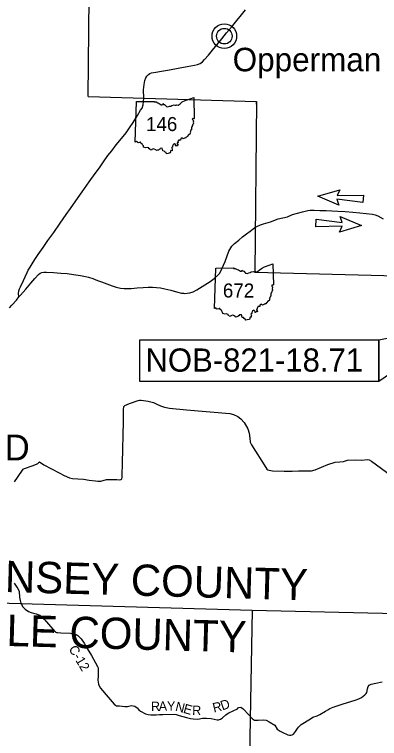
# Model space of a CAD drawing. Extents: x 0 to 34, y 0 to 22.
# Drawn here: x 22.078 to 24.277, y 13.537 to 17.905 of the extents above; entities that cross this region are included whole.
import ezdxf

# ---------------------------------------------------------------- set-up
doc = ezdxf.new("R2010")
doc.units = 0
for name, color, linetype in [('Default', 7, 'Continuous'), ('GM_X_County_Road_Text', 7, 'Continuous'), ('GM_X_State_Route', 7, 'Continuous'), ('GM_X_Township', 7, 'Continuous'), ('GM_X_Unincorporated', 7, 'Continuous'), ('GM_X_Unincorporated_Text', 7, 'Continuous'), ('TX_P_1', 7, 'Continuous')]:
    doc.layers.add(name, color=color, linetype=linetype)

msp = doc.modelspace()

# ---------------------------------------------------------------- linework, layer by layer
at = {"layer": 'Default'}
for p, q in [((22.8057, 17.1347), (22.8136, 17.3788)), ((23.9046, 16.8078), (24.0377, 16.8476)), ((24.0377, 16.8476), (24.0222, 16.8128)), ((24.0222, 16.8128), (24.1797, 16.8155)), ((24.1797, 16.8155), (24.1773, 16.7708)), ((24.0327, 16.7539), (23.9046, 16.8078)), ((24.1773, 16.7708), (24.0209, 16.7904)), ((24.0209, 16.7904), (24.0327, 16.7539)), ((24.0527, 16.6499), (24.0409, 16.6862)), ((24.0409, 16.6862), (24.169, 16.6324)), ((23.8939, 16.6247), (23.8963, 16.6694)), ((23.8963, 16.6694), (24.0527, 16.6499)), ((24.0514, 16.6272), (23.8939, 16.6247)), ((24.169, 16.6324), (24.0358, 16.5925)), ((24.0358, 16.5925), (24.0514, 16.6272)), ((23.2832, 16.1306), (23.291, 16.3746))]:
    msp.add_line(p, q, dxfattribs=at)
for points in [[(22.8136, 17.3788), (22.9218, 17.3803), (22.9201, 17.3774), (22.9303, 17.3768), (22.9411, 17.3715), (22.9503, 17.3683), (22.9615, 17.3605), (22.9682, 17.3606), (22.9711, 17.367), (22.9762, 17.362), (22.9823, 17.3612), (22.9929, 17.3495), (23.0016, 17.347), (23.012, 17.351), (23.0197, 17.3516), (23.0255, 17.3556), (23.0403, 17.359), (23.0445, 17.3569), (23.0523, 17.3574), (23.0563, 17.3588), (23.0632, 17.3575), (23.0752, 17.3664), (23.0876, 17.3768), (23.1068, 17.3867), (23.1352, 17.396), (23.1579, 17.4044), (23.1611, 17.2778)], [(23.1611, 17.2778), (23.1578, 17.276), (23.1526, 17.2768), (23.1491, 17.2733), (23.1535, 17.2674), (23.1555, 17.2611), (23.1537, 17.2542), (23.1555, 17.2485), (23.1543, 17.2438), (23.151, 17.239), (23.1499, 17.2345), (23.1471, 17.2297), (23.1473, 17.2271), (23.1447, 17.225), (23.1452, 17.217), (23.1438, 17.2127), (23.1443, 17.2089), (23.14, 17.2079), (23.141, 17.2048), (23.1382, 17.2023), (23.1388, 17.1982), (23.1357, 17.1955), (23.1387, 17.1902), (23.1363, 17.1885), (23.1343, 17.1821), (23.1288, 17.1807), (23.1179, 17.169), (23.114, 17.1645), (23.1096, 17.1634), (23.1072, 17.1588), (23.1018, 17.1588), (23.0937, 17.1556), (23.0884, 17.161), (23.0792, 17.1545), (23.0782, 17.1468), (23.0666, 17.1471), (23.067, 17.1432), (23.0644, 17.1421), (23.0621, 17.1383), (23.0634, 17.1314), (23.0579, 17.1297), (23.0586, 17.1257), (23.0621, 17.1233), (23.0637, 17.1157), (23.0579, 17.1172), (23.0531, 17.1108), (23.0482, 17.1123), (23.0498, 17.1177), (23.0416, 17.1243), (23.0338, 17.1191), (23.0297, 17.1107), (23.0297, 17.105), (23.0238, 17.1017), (23.0276, 17.0937), (23.0269, 17.0883), (23.027, 17.083), (23.0197, 17.0833), (23.0153, 17.0692)], [(23.0153, 17.0692), (23.0027, 17.0666), (22.994, 17.065), (22.9909, 17.0713), (22.9846, 17.0747), (22.9805, 17.0811), (22.9715, 17.0819), (22.9694, 17.0908), (22.9684, 17.0979), (22.9561, 17.0961), (22.9528, 17.0918), (22.9484, 17.0906), (22.9458, 17.0862), (22.9398, 17.0858), (22.9335, 17.0837), (22.9293, 17.088), (22.9188, 17.0924), (22.9141, 17.0946), (22.9043, 17.0912), (22.9022, 17.0871), (22.8944, 17.0889), (22.8925, 17.0935), (22.8878, 17.0949), (22.8868, 17.0997), (22.8766, 17.1023), (22.8689, 17.1013), (22.8552, 17.1052), (22.8544, 17.1116), (22.8497, 17.1194), (22.8474, 17.1248), (22.8387, 17.1288), (22.8369, 17.1353), (22.8342, 17.1351), (22.8317, 17.1325), (22.822, 17.1313), (22.8182, 17.1339), (22.8128, 17.1385), (22.8057, 17.1347)], [(22.104, 16.2014), (22.1143, 16.2115), (22.1452, 16.2469), (22.1757, 16.2842), (22.2009, 16.3131), (22.222, 16.3359), (22.2326, 16.3446), (22.2432, 16.3489), (22.2545, 16.3508), (22.2712, 16.3509), (22.3125, 16.3477), (22.3568, 16.3452), (22.395, 16.3416), (22.4322, 16.3361), (22.475, 16.3299), (22.5064, 16.3251), (22.5231, 16.3211), (22.55, 16.3114), (22.5777, 16.3005), (22.6028, 16.2915), (22.6331, 16.2803), (22.6665, 16.2684), (22.6907, 16.2605), (22.7169, 16.2542), (22.7389, 16.2517), (22.7597, 16.2518), (22.7809, 16.2527), (22.8161, 16.2559), (22.8521, 16.2587), (22.8827, 16.2607), (22.9092, 16.2605), (22.9342, 16.2583), (22.957, 16.2554), (22.9843, 16.2491), (23.0191, 16.2413), (23.0544, 16.2324), (23.0839, 16.2242), (23.0955, 16.2228), (23.101, 16.222), (23.118, 16.2229), (23.1351, 16.2264), (23.1551, 16.2325), (23.1759, 16.2432), (23.2573, 16.2946), (23.2807, 16.3131), (23.2985, 16.3286), (23.3141, 16.345), (23.3262, 16.3706), (23.3461, 16.4146), (23.3695, 16.4766), (23.3869, 16.5075), (23.4032, 16.5238), (23.4291, 16.5437), (23.4522, 16.5629), (23.476, 16.5821), (23.4969, 16.5973), (23.5243, 16.6175), (23.5267, 16.6194), (23.5381, 16.6261), (23.5598, 16.6357), (23.5771, 16.6421), (23.6205, 16.6549), (23.6673, 16.6712), (23.7218, 16.6847), (23.7536, 16.6987), (23.8129, 16.7147), (23.8288, 16.7193), (23.8447, 16.7221), (23.8594, 16.7236), (23.8833, 16.7234), (23.9178, 16.7232), (23.9552, 16.7222), (23.9893, 16.7205), (24.0264, 16.718), (24.0692, 16.716), (24.1155, 16.7128), (24.1583, 16.7092), (24.1969, 16.7052), (24.2348, 16.7005), (24.2515, 16.6964), (24.2666, 16.6893), (24.2993, 16.6724)], [(23.291, 16.3746), (23.3992, 16.3762), (23.3976, 16.3732), (23.4077, 16.3726), (23.4186, 16.3674), (23.4278, 16.3641), (23.4389, 16.3564), (23.4457, 16.3564), (23.4485, 16.3628), (23.4536, 16.3579), (23.4598, 16.357), (23.4703, 16.3453), (23.4791, 16.3428), (23.4895, 16.3468), (23.4972, 16.3475), (23.5029, 16.3514), (23.5178, 16.3548), (23.522, 16.3528), (23.5298, 16.3532), (23.5338, 16.3547), (23.5407, 16.3533), (23.5526, 16.3623), (23.5651, 16.3727), (23.5842, 16.3826), (23.6127, 16.3919), (23.6353, 16.4003), (23.6386, 16.2736)], [(23.6386, 16.2736), (23.6353, 16.2719), (23.6301, 16.2727), (23.6266, 16.2692), (23.6309, 16.2632), (23.6329, 16.2569), (23.6311, 16.2501), (23.6329, 16.2444), (23.6317, 16.2396), (23.6285, 16.2348), (23.6273, 16.2303), (23.6245, 16.2256), (23.6247, 16.2229), (23.6222, 16.2209), (23.6226, 16.2129), (23.6213, 16.2085), (23.6218, 16.2047), (23.6174, 16.2037), (23.6184, 16.2006), (23.6157, 16.1982), (23.6163, 16.194), (23.6132, 16.1913), (23.6162, 16.186), (23.6138, 16.1844), (23.6118, 16.1779), (23.6063, 16.1766), (23.5953, 16.1648), (23.5914, 16.1603), (23.5871, 16.1592), (23.5846, 16.1546), (23.5793, 16.1546), (23.5711, 16.1514), (23.5659, 16.1569), (23.5567, 16.1503), (23.5556, 16.1427), (23.5441, 16.1429), (23.5445, 16.1391), (23.5419, 16.138), (23.5395, 16.1341), (23.5409, 16.1273), (23.5354, 16.1255), (23.5361, 16.1215), (23.5396, 16.1192), (23.5411, 16.1115), (23.5353, 16.113), (23.5306, 16.1066), (23.5257, 16.1082), (23.5273, 16.1136), (23.519, 16.1202), (23.5113, 16.1149), (23.5072, 16.1065), (23.5071, 16.1009), (23.5013, 16.0975), (23.5051, 16.0896), (23.5043, 16.0841), (23.5045, 16.0789), (23.4972, 16.0791), (23.4928, 16.0651)], [(22.0485, 16.1355), (22.062, 16.1504), (22.0887, 16.1812), (22.104, 16.2014)], [(23.4928, 16.0651), (23.4802, 16.0624), (23.4715, 16.0608), (23.4683, 16.0672), (23.4621, 16.0706), (23.458, 16.0769), (23.449, 16.0778), (23.4469, 16.0866), (23.4459, 16.0937), (23.4335, 16.092), (23.4302, 16.0876), (23.4258, 16.0864), (23.4233, 16.082), (23.4173, 16.0817), (23.4109, 16.0796), (23.4067, 16.0839), (23.3963, 16.0883), (23.3916, 16.0905), (23.3817, 16.087), (23.3797, 16.0829), (23.3719, 16.0847), (23.37, 16.0893), (23.3653, 16.0907), (23.3642, 16.0955), (23.3541, 16.0981), (23.3463, 16.0971), (23.3327, 16.101), (23.3318, 16.1074), (23.3272, 16.1152), (23.3248, 16.1206), (23.3162, 16.1247), (23.3144, 16.1312), (23.3117, 16.131), (23.3091, 16.1284), (23.2995, 16.1271), (23.2957, 16.1298), (23.2903, 16.1343), (23.2832, 16.1306)], [(22.0771, 15.0851), (22.0962, 15.1109), (22.1293, 15.1623), (22.1384, 15.1667), (22.1835, 15.1828), (22.21, 15.1916), (22.2191, 15.1971), (22.2283, 15.2068), (22.2544, 15.1891), (22.346, 15.1397), (22.3769, 15.1229), (22.4081, 15.1098), (22.4271, 15.1056), (22.4593, 15.1036), (22.4933, 15.102), (22.5274, 15.0962), (22.5654, 15.0909), (22.5805, 15.0888), (22.5975, 15.0891), (22.6328, 15.0989), (22.6502, 15.0996), (22.6944, 15.0989), (22.7107, 15.098), (22.7178, 15.1001), (22.7238, 15.1028), (22.7259, 15.1108), (22.7272, 15.1229), (22.7288, 15.1998), (22.734, 15.4496), (22.7353, 15.523), (22.7359, 15.5351), (22.7373, 15.5408), (22.7432, 15.5466), (22.7709, 15.5585), (22.8228, 15.5769), (22.831, 15.5785), (22.8401, 15.5779), (22.8833, 15.5719), (22.9145, 15.5642), (22.9354, 15.5551), (22.9571, 15.5449), (22.9822, 15.5363), (23.0126, 15.5297), (23.1141, 15.5191), (23.3756, 15.4974), (23.3972, 15.4925), (23.4232, 15.4798), (23.4423, 15.4654), (23.4613, 15.4426), (23.4827, 15.4063), (23.4923, 15.38), (23.4963, 15.3483), (23.4971, 15.3249), (23.5057, 15.308), (23.5925, 15.1723), (23.5991, 15.1622), (23.6048, 15.1589), (23.6128, 15.1553), (23.6329, 15.1511), (23.7021, 15.1497), (23.7505, 15.1508), (23.7898, 15.1517), (23.8668, 15.1528), (23.8887, 15.1574), (23.9663, 15.1898), (24.0106, 15.2039), (24.0378, 15.2055), (24.0605, 15.2078), (24.0845, 15.217), (24.1351, 15.2186), (24.1706, 15.2171), (24.205, 15.22), (24.2141, 15.2186), (24.2294, 15.2095), (24.3496, 15.122)], [(22.1175, 14.3533), (22.1139, 14.3702), (22.1095, 14.3894), (22.107, 14.4236), (22.0938, 14.4507), (22.0776, 14.4746)], [(22.1175, 14.3533), (22.1263, 14.334), (22.1419, 14.3182), (22.162, 14.3037), (22.1788, 14.2983), (22.1929, 14.2929), (22.208, 14.2896), (22.2294, 14.2811), (22.2409, 14.2723), (22.2567, 14.2578), (22.3083, 14.1978), (22.3234, 14.181), (22.3261, 14.1785), (22.331, 14.1762), (22.3359, 14.1763), (22.3575, 14.1752), (22.4142, 14.1732), (22.4389, 14.1694), (22.4499, 14.1655), (22.4594, 14.1588), (22.4795, 14.138), (22.4973, 14.1129), (22.5156, 14.0811), (22.5413, 14.038), (22.5787, 13.972), (22.5818, 13.9645), (22.5824, 13.9532), (22.5808, 13.9145), (22.5805, 13.8903), (22.5811, 13.8774), (22.5832, 13.8642), (22.5875, 13.8552), (22.5968, 13.8406), (22.6416, 13.7876), (22.679, 13.7444), (22.6855, 13.7384), (22.6931, 13.7352), (22.7102, 13.7336), (22.7424, 13.73), (22.7582, 13.731), (22.7831, 13.7364), (22.7922, 13.735), (22.802, 13.7326), (22.8108, 13.7274), (22.8166, 13.7215), (22.8274, 13.7099), (22.8377, 13.7025), (22.8667, 13.6864), (22.8823, 13.6817), (22.8986, 13.6798), (22.9322, 13.6807), (22.9511, 13.6826), (22.9707, 13.6829), (23.0395, 13.6845), (23.052, 13.6825), (23.0699, 13.6771), (23.1143, 13.6632), (23.1375, 13.6575), (23.1545, 13.6552), (23.1818, 13.6549), (23.2108, 13.6592), (23.224, 13.6602), (23.235, 13.6608), (23.263, 13.6575), (23.2986, 13.6502), (23.3077, 13.65), (23.3198, 13.6532), (23.3317, 13.6629), (23.3511, 13.6799), (23.3585, 13.6868), (23.3682, 13.6923), (23.4219, 13.7163), (23.4221, 13.7167)], [(23.4221, 13.7167), (23.4278, 13.7247), (23.4413, 13.7263), (23.4551, 13.7166), (23.4896, 13.6795), (23.5125, 13.6555), (23.5243, 13.6474), (23.5454, 13.6474), (23.5804, 13.6506), (23.5946, 13.6474), (23.6125, 13.6372), (23.6463, 13.6169), (23.6598, 13.5941), (23.6786, 13.5812), (23.7026, 13.5703), (23.7129, 13.5663), (23.7254, 13.5601), (23.7357, 13.5569), (23.7429, 13.5566), (23.7508, 13.5598), (23.7583, 13.5645), (23.7705, 13.5798), (23.7838, 13.5986), (23.7893, 13.6067), (23.7941, 13.6128), (23.806, 13.6214), (23.8606, 13.6568), (23.8752, 13.6654), (23.9023, 13.6742), (23.9177, 13.682), (23.9517, 13.7023), (23.9663, 13.7113), (23.9768, 13.7179), (23.9982, 13.7267), (24.0572, 13.7466), (24.1301, 13.768), (24.1534, 13.7768), (24.1684, 13.7842), (24.1893, 13.8005), (24.1967, 13.8082), (24.2008, 13.8151), (24.2038, 13.8371), (24.2088, 13.852), (24.2147, 13.8596), (24.2264, 13.8655), (24.255, 13.871), (24.293, 13.8792)]]:
    msp.add_lwpolyline(points, dxfattribs=at)
at = {"layer": 'GM_X_State_Route'}
msp.add_lwpolyline([(22.104, 16.2014), (22.1024, 16.2207), (22.1038, 16.237), (22.1075, 16.2502), (22.1134, 16.2621), (22.1324, 16.2995), (22.1422, 16.3219), (22.1546, 16.3488), (22.1609, 16.3621), (22.1722, 16.3803), (22.1895, 16.4099), (22.2034, 16.4327), (22.2211, 16.4574), (22.2508, 16.5), (22.279, 16.541), (22.314, 16.5896), (22.3531, 16.6455), (22.3893, 16.6979), (22.4157, 16.7342), (22.4469, 16.78), (22.4859, 16.835), (22.5279, 16.895), (22.564, 16.9454), (22.5889, 16.9801), (22.6145, 17.0164), (22.6409, 17.0542), (22.6633, 17.0832), (22.6912, 17.118), (22.7221, 17.1574), (22.7497, 17.1914), (22.7716, 17.2201), (22.7932, 17.2529), (22.818, 17.2956), (22.8373, 17.328), (22.8468, 17.3394), (22.8536, 17.3596), (22.8567, 17.3993), (22.8558, 17.4494), (22.8581, 17.4823), (22.8634, 17.507), (22.8685, 17.5222), (22.8748, 17.5333), (22.8842, 17.5425), (22.8939, 17.5483), (22.9041, 17.5518), (22.9298, 17.5563), (22.9634, 17.5623), (23.0117, 17.5712), (23.0633, 17.5806), (23.1184, 17.5907), (23.1626, 17.5984), (23.1807, 17.6028), (23.1965, 17.6094), (23.2107, 17.6194), (23.2231, 17.6324), (23.2462, 17.6596), (23.2708, 17.6898), (23.2984, 17.7227), (23.3263, 17.7571), (23.3561, 17.7934), (23.3844, 17.8286), (23.4172, 17.868), (23.4452, 17.9024), (23.4705, 17.9333)], dxfattribs=at)
at = {"layer": 'GM_X_Township'}
for p, q in [((22.5206, 17.4094), (22.5575, 20.4019)), ((22.5206, 17.4094), (23.5353, 17.3801)), ((23.5353, 17.3801), (23.5249, 16.3502)), ((23.535, 17.3632), (23.5353, 17.3801)), ((23.535, 17.3632), (23.5353, 17.3801)), ((23.5249, 16.3502), (24.5317, 16.3233)), ((21.4596, 14.3709), (23.5089, 14.3112)), ((23.5089, 14.3112), (23.4636, 11.7712)), ((23.5089, 14.3112), (24.5006, 14.2876))]:
    msp.add_line(p, q, dxfattribs=at)
at = {"layer": 'GM_X_Unincorporated'}
for radius in [0.0742, 0.0471]:
    msp.add_circle((23.3421, 17.774), radius, dxfattribs=at)
at = {"layer": 'TX_P_1'}
for points in [[(24.2721, 15.9418), (24.7897, 16.045), (24.2721, 15.69)], [(22.833, 15.9418), (24.2721, 15.9418), (24.2721, 15.69), (22.833, 15.69)]]:
    msp.add_lwpolyline(points, close=True, dxfattribs=at)

# ---------------------------------------------------------------- texts
at = {"layer": 'Default'}
for s, p in [('146', (22.87, 17.2016)), ('672', (23.3333, 16.1974))]:
    msp.add_text(s, height=0.08462, dxfattribs=at).set_placement(p)
at = {"layer": 'GM_X_County_Road_Text'}
for s, rotation, p in [('C-12', 300.7441, (22.4019, 14.0787)), ('R', 1.374, (22.9005, 13.7027)), ('A', 1.3698, (22.9471, 13.7038)), ('Y', 0.2732, (22.9967, 13.705)), ('N', 345.6881, (23.0428, 13.7057)), ('R', 13.5478, (23.279, 13.6938)), ('D', 19.1785, (23.33, 13.7064)), ('E', 343.7773, (23.0907, 13.6935)), ('R', 359.2429, (23.1479, 13.6792))]:
    msp.add_text(s, height=0.0567, rotation=rotation, dxfattribs=at).set_placement(p)
at = {"layer": 'GM_X_Unincorporated_Text'}
for s, height, rotation, p in [('Opperman', 0.14175, 0, (23.3922, 17.562)), ('CUMBERLAND', 0.15568, 0, (20.7118, 15.2147)), ('GUERNSEY COUNTY', 0.189, 358.4232, (21.2882, 14.4412)), ('NOBLE COUNTY', 0.189, 358.4232, (21.4801, 14.1108))]:
    msp.add_text(s, height=height, rotation=rotation, dxfattribs=at).set_placement(p)
at = {"layer": 'TX_P_1'}
msp.add_text('NOB-821-18.71', height=0.14, dxfattribs=at).set_placement((22.8668, 15.7502))

doc.saveas('drawing.dxf')
